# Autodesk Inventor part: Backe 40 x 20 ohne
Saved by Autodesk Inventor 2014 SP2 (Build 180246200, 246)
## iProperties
Created: 2015-06
Part Number: Backe 40 x 20 ohne
Material: Generisch
Document SubType Name: Modeling
Designer: e_krauts
Density: 1 g/cm^3
Appearance: Vorgabe
Mass: 455.967 g
Surface Area: 736.38 cm^2
Volume: 455.967 cm^3
Sending System: SolidWorks 2011
Last Author: e_boekem
Author: e_krauts
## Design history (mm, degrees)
node "Backe 40 x 20 ohne.ipt1"
node "Fase11"
node "Aufsatz-Linear austragen5"
node "Basis1"
node "Basis2"
